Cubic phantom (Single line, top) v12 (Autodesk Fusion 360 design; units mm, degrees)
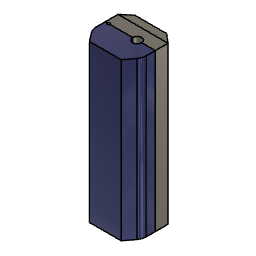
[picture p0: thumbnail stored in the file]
sketch "Side view" plane through (0, 0, 0) normal (0, 0, 1) x axis (1, 0, 0)
  line L1 (7, 0) -> (-7, 0)
  line L2 (11, 5.3082) -> (7, 0)
  line L3 (-11, 5.3082) -> (-7, 0)
  line L4 (-11, 5.3082) -> (11, 5.3082)
  line L5 (-11, 11) -> (-11, 5.3082)
  line L6 (11, 11) -> (11, 5.3082)
  line L7 (11, 11) -> (-11, 11)
  line L8 (8.3709, 14.7) -> (-2.3291, 14.7)
  line L9 (8.3709, 4) -> (8.3709, 14.7)
  line L10 (-2.3291, 4) -> (8.3709, 4)
  line L11 (-2.3291, 14.7) -> (-2.3291, 4)
  line L12 (3.0209, 14.7) -> (3.0209, 4)
  line L13 (1.3209, 8.3) -> (1.3209, 11)
  line L14 (4.7209, 8.3) -> (1.3209, 8.3)
  line L15 (4.7209, 8.3) -> (4.7209, 11)
  line L16 (-11, 16.6082) -> (-11, 11)
  line L17 (11, 16.6082) -> (-11, 16.6082)
  line L18 (11, 11) -> (11, 16.6082)
  line L19 (-7, 19.9646) -> (-11, 16.6082)
  line L20 (7, 19.9646) -> (-7, 19.9646)
  line L21 (11, 16.6082) -> (7, 19.9646)
  line L22 (-7, 19.9646) -> (-7, 0)
  circle C1 centre (3.0209, 11) radius 0.6
  circle C2 centre (3.0209, 11) radius 2
  circle C3 centre (-9.5, 11) radius 0.6
  circle C4 centre (3.0209, 11) radius 1.7
  circle C5 centre (3.0209, 16.6082) radius 0.75
  circle C6 centre (3.0209, 16.6082) radius 1
  point P1 (0, 0)
  point P5 (-11, 5.3082)
  point P6 (-11, 5.3082)
  point P13 (3.0209, 4)
  point P14 (3.0209, 14.7)
  point P15 (3.0209, 11)
  point P16 (3.0209, 11)
  point P17 (-9.5, 11)
  point P19 (1.3209, 11)
  point P22 (4.7209, 11)
  point P25 (-7, 19.9646)
  point P27 (-7, 19.9646)
  point P28 (3.0209, 16.6082)
  point P18 (3.0209, 11)
  point P2 (-7, 0)
  point P3 (7, 0)
  point P4 (11, 5.3082)
  point P9 (-2.3291, 14.7)
  point P10 (8.3709, 14.7)
  point P20 (1.3209, 8.3)
  point P7 (-11, 11)
  point P24 (11, 16.6082)
  horizontal L1
  midpoint P1 L1
  horizontal L4
  coincident P5 P6
  equal L2 L3
  perpendicular L4 L5
  perpendicular L4 L6
  horizontal L7
  horizontal L8
  vertical L9
  horizontal L10
  vertical L11
  equal L10 L11
  midpoint L10 P13
  midpoint L8 P14
  coincident L12 P15
  concentric C1 C2
  coincident L7 P16
  coincident L7 P17
  equal C1 C3
  concentric C1 C4
  coincident C4 P19
  coincident L7 P19
  tangent C4 L13
  perpendicular L7 L13
  perpendicular L12 L14
  coincident C4 P22
  coincident L7 P22
  vertical L15
  perpendicular L7 L16
  perpendicular L5 L17
  vertical L18
  horizontal L20
  equal L19 L21
  perpendicular L17 L22
  coincident P25 P27
  coincident L17 P28
  vertical P18 P28
  concentric C5 C6
  dimension "d1" distance P2 P3 = 14
  dimension "d2" angle L1 L2 = 53
  dimension "d4" distance P4 P6 = 22
  dimension "d21" distance P9 P10 = 10.7
  dimension "d23" diameter C1 = 1.2
  dimension "d24" diameter C2 = 4
  dimension "d58" diameter C4 = 3.4
  dimension "d59" distance P19 P20 = 2.7
  dimension "d77" distance P7 P17 = 1.5
  dimension "d78" distance L1 L7 = 11
  dimension "d85" distance P4 P24 = 11.3
  dimension "d86" angle L17 L21 = 40
  dimension "d87" distance L1 L20 = 19.9646
  dimension "d92" diameter C6 = 2
  dimension "d93" diameter C5 = 1.5
  dimension "d109" distance L6 L9 = 2.6291
  dimension "d114" distance L10 P18 = 7
extrude "Extrude1" new body sketch "Side view" profile of L1 L2 L3 L5 L6 L7 against normal blind 69 bodies "Bottom"
extrude "Extrude15" new body sketch "Side view" profile of L7 L8 L9 L11 C1 C2 C3 C4 L16 L18 L19 L20 L21 C5 C6 to an object bodies "MIddle"
fillet "Fillet1" radius 5 5
sketch "Tubing map (top)" plane through (0, 11, 0) normal (0, 1, 0) x axis (-1, 0, 0)
  line L1 (-11, 0) -> (11, 0)
  line L2 (-11, -69) -> (-11, 0)
  line L3 (11, -69) -> (-11, -69)
  line L4 (11, 0) -> (11, -69)
  line L5 (-3.0209, -69) -> (-3.0209, 0)
  line L6 (9.5, -30.8) -> (9.5, 0)
  line L7 (9.5, -30.8) -> (5.8, -30.8)
  line L8 (5.8, -30.8) -> (5.8, -34.5)
  line L9 (-3.0209, -34.5) -> (5.8, -34.5)
  line L10 (9.5, -69) -> (9.5, -30.8)
  circle C1 centre (3.1028, -34.5) radius 3.3
  arc A1 centre (5.8, -30.8) radius 3.7 clockwise from (9.5, -30.8) to (5.8, -34.5)
  point P7 (-3.0209, 0)
  point P8 (-3.0209, 0)
  point P9 (-3.0209, -69)
  point P12 (5.8, -30.8)
  point P14 (5.8, -30.8)
  point P15 (5.8, -30.8)
  point P16 (-3.0209, -34.5)
  point P17 (-3.0209, -3)
  point P18 (-3.0209, -66)
  point P10 (9.5, 0)
  point P19 (9.5, 0)
  point P6 (3.1028, -34.5)
  point P20 (9.5, -69)
  point P11 (9.5, -30.8)
  coincident P7 P8
  coincident L3 P9
  perpendicular L3 L5
  perpendicular L1 L6
  coincident P12 P14
  coincident P12 P15
  tangent L6 A1
  coincident L5 P16
  tangent A1 L9
  coincident L5 P17
  coincident L5 P18
  coincident P10 P19
  coincident P6 L9
  coincident L3 P20
  tangent A1 L10
  dimension "d13" diameter C1 = 6.6
  dimension "d25" angle L7 L8 = 90
  dimension "d41" distance P8 P17 = 3
  dimension "d42" distance P9 P18 = 3
  dimension "d63" distance P8 P16 = 34.5
  dimension "d64" distance P8 P9 = 69
  dimension "d110" distance P11 P12 = 3.7
work_plane "WorkPlane2" AlongDistance 15.908
split "Split1" bodies "Top"
sketch "Contrast tube" plane through (0, 16.6082, 0) normal (0, 1, 0) x axis (-1, 0, 0)
  line L1 (-11, -69) -> (-11, 0)
  line L2 (11, -69) -> (-11, -69)
  line L3 (11, 0) -> (11, -69)
  line L4 (-11, 0) -> (11, 0)
  line L5 (-3.0209, -69) -> (-3.0209, 0)
  line L6 (-3.0209, -66) -> (-3.0209, -3)
  point P6 (-3.0209, 0)
  point P7 (-3.0209, 0)
  point P8 (-3.0209, -69)
  point P9 (-3.0209, -3)
  point P10 (-3.0209, -66)
  coincident P6 P7
  coincident L2 P8
  perpendicular L2 L5
  coincident L5 P9
  coincident L5 P10
  dimension "d98" distance P7 P9 = 3
  dimension "d99" distance P8 P10 = 3
work_plane "WorkPlane1" sketch "Side view" AlongDistance -34.5
sketch "Rotation axix" plane through (0, 5.6, -34.5) normal (0, 0, 1) x axis (1, 0, 0)
  line L1 (3.1709, 9.6865) -> (3.1709, 5.6)
  point P2 (3.0709, 5.6)
  point P3 (3.1709, 5.6)
  coincident P2 P3
  vertical L1
extrude "Extrude2" cut sketch "Tubing map (top)" profile of C1 against normal blind 10
extrude "Extrude19" cut sketch "Tubing map (top)" profile of C1 to an object
sweep "Sweep1" sketch "Side view" TwistAngle 0 TaperAngle 0 bodies "Waste line"
sweep "Sweep2" sketch "Side view" TwistAngle 0 TaperAngle 0
extrude "Extrude3" sketch "Side view" profile of L7 L8 L9 L10 L11 C1 C2 C4 L13 L14 L15 blind -18.8 bodies "Tubes"
copy_paste_bodies "CopyPasteBodies1"
extrude "Extrude4" sketch "Side view" profile of L7 L8 L9 L10 L11 C1 C2 C4 L13 L14 L15 blind 18.8 bodies "output"
copy_paste_bodies "CopyPasteBodies2"
copy_paste_bodies "CopyPasteBodies4"
extrude "Extrude6" sketch "Side view" profile of L7 C1 C2 C4 L13 L15 blind -3 bodies "sleeve"
extrude "Extrude8" sketch "Side view" profile of L7 C1 C2 C4 L13 L15 blind -3 bodies "sleeve (1)"
extrude "Extrude7" sketch "Side view" profile of L7 C1 C2 C4 L13 L15 blind 3 bodies "sleeve (2)"
extrude "Extrude5" sketch "Side view" profile of L7 C1 C2 C4 L13 L15 blind 3 bodies "sleeve (3)"
extrude "Extrude9" sketch "Side view" profile of L7 C1 C2 C4 L13 L14 L15 blind 7.4 bodies "tee"
copy_paste_bodies "CopyPasteBodies3"
extrude "Extrude14" sketch "Side view" profile of L7 C1 C2 C4 L13 L14 L15 blind 7.4
move "Move2" RotateAngle -90
extrude "Extrude10" sketch "Side view" profile of L7 C1 C2 blind 2 bodies "Waste line"
extrude "Extrude11" sketch "Side view" profile of L7 C1 C2 blind -2 bodies "Waste line"
extrude "Extrude12" sketch "Side view" profile of L7 C1 C2 C4 L13 L14 L15 blind 7.4
extrude "Extrude13" sketch "Side view" profile of L7 C1 C2 blind 2
combine "Combine2" bodies "tee (1)", "output"
move "Move3" RotateAngle -90
combine "Combine3" bodies "Tubes with sleeves (1)", "sleeve", "sleeve (1)", "sleeve (2)", "sleeve (3)", "Waste line", "tee"
extrude "Extrude16" sketch "Side view" profile of C5 to an object bodies "Contrast tube"
extrude "Extrude17" sketch "Side view" profile of C5 C6 blind 2
extrude "Extrude18" sketch "Side view" profile of C5 C6 blind -2
base_feature "Base Feature1"
work_plane "WorkPlane1" AlongDistance -2 named "d1_1"
split "Split1"
move "Move1"
remove_body "RemoveBody1"
remove_body "RemoveBody2"
remove_body "RemoveBody3"
remove_body "RemoveBody6"
remove_body "RemoveBody9"
combine "Combine7"
combine "Combine8" bodies "sleeve (3)", "sleeve (2)", "sleeve (1)", "sleeve", "Tubes with sleeves"
combine "Combine9"
combine "Combine10"
combine "Combine11"
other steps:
base_feature "Base Feature1" bodies "Tubes with sleeves"
base_feature "Base Feature2"
base_feature "Base Feature4" bodies "output", "Tubes with sleeves"
base_feature "Base Feature3" bodies "tee (1)"
create_component "CreateComponent1"
named bodies: "Bottom", "Waste line", "Tubes", "Tubes with sleeves", "output", "tee", "tee (1)", "sleeve (3)", "sleeve", "sleeve (1)", "sleeve (2)", "MIddle", "Top", "Contrast tube", "Tubes with sleeves (1)"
